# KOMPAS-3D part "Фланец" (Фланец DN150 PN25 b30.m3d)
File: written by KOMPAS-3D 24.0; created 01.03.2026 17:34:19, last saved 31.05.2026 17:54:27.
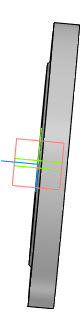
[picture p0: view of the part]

Document properties: Автор: R2D2; Полное имя файла: E:\Работа\Зайцев\GVWR2121M-2W-F-ОСТ Задвижка клиновая 30с964нж DN.ru Ду50-300 Ру25\исходные материалы\DN150\Фланец DN150 PN25 b30.m3d

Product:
- Part/product: Фланец
    Масса: 10.851235
    additional columns: Типовые

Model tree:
1. Эскиз:2
2. Элемент вращения:1
     Угол 1 = 360
3. Эскиз:3  (with: Грань.Элемент вращения:1)
4. Элемент выдавливания:2
     Расстояние 2 = 27
5. Массив по концентрической сетке:1  (with: Элемент выдавливания:2, Эскиз:3, Грань.Элемент вращения:1)  (8 pattern instances)
     Шаг 2 = 360
6. Эскиз:4  (with: Грань.Элемент вращения:1)
7. Элемент выдавливания:3
     Расстояние 2 = 4

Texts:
  Линейный размер с обрывом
